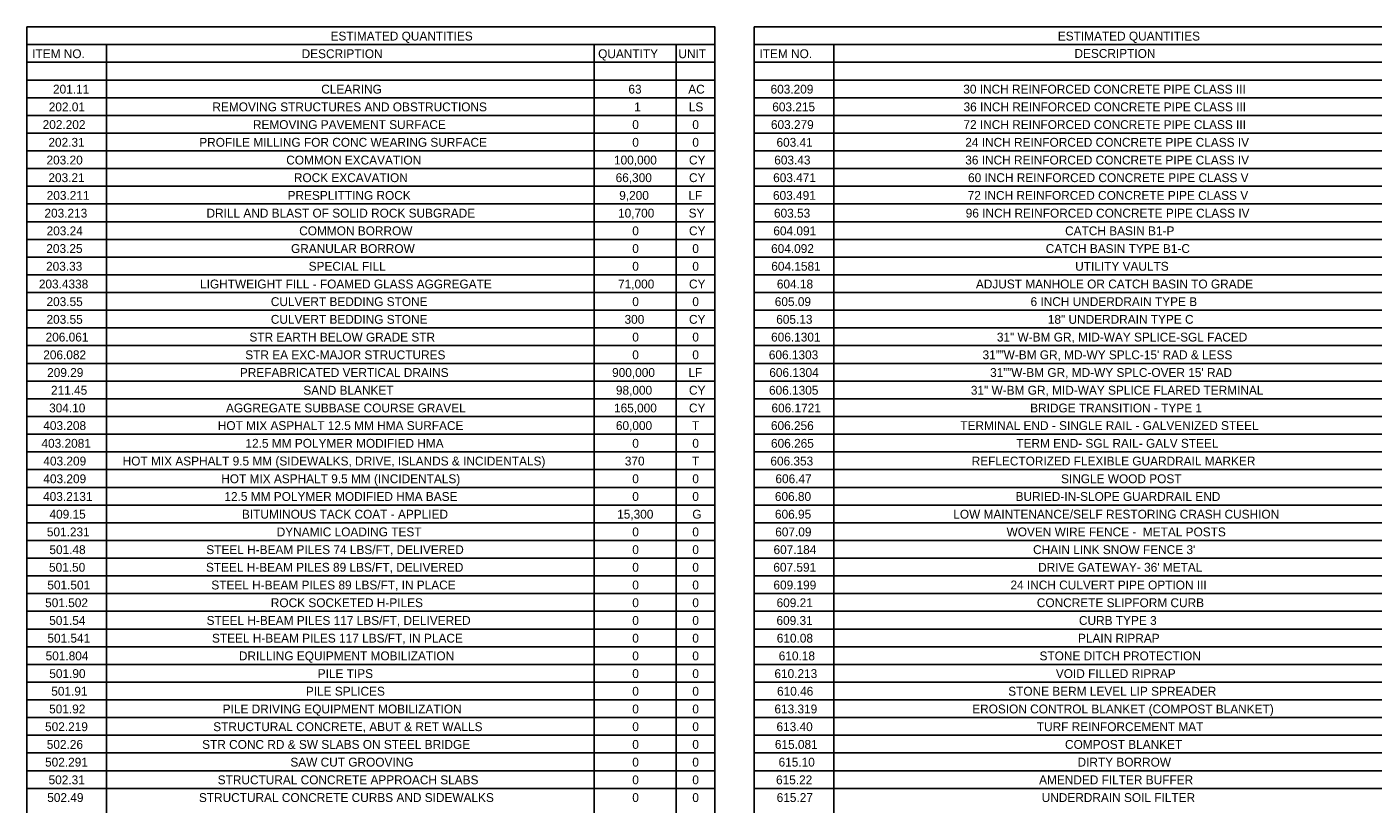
# Model space of a CAD drawing. Extents: x -18.7 to 5.6, y -2.7 to 4.
# Drawn here: x 3.137 to 4.632, y 0.887 to 1.751 of the extents above; entities that cross this region are included whole.
import ezdxf

# ---------------------------------------------------------------- set-up
doc = ezdxf.new("R2010")
doc.units = 0
doc.layers.add('ANNOTATION', color=7, linetype='Continuous')
doc.layers.add('BORDER', color=7, linetype='Continuous')

msp = doc.modelspace()

# ---------------------------------------------------------------- linework, layer by layer
at = {"layer": 'BORDER'}
for p, q in [((3.1369, 1.7315), (3.9012, 1.7315)), ((3.2255, 1.7315), (3.2255, 0.0189)), ((3.7669, 1.7315), (3.7669, 0.0189)), ((3.8583, 1.7315), (3.8583, 0.0189)), ((3.9448, 1.7315), (4.8091, 1.7315)), ((4.0334, 1.7315), (4.0334, 0.0189)), ((3.1369, 1.7119), (3.9012, 1.7119)), ((3.9448, 1.7119), (4.8091, 1.7119)), ((3.1369, 1.6922), (3.9012, 1.6922)), ((3.9448, 1.6922), (4.8091, 1.6922)), ((3.1369, 1.6725), (3.9012, 1.6725)), ((3.9448, 1.6725), (4.8091, 1.6725)), ((3.1369, 1.6528), (3.9012, 1.6528)), ((3.9448, 1.6528), (4.8091, 1.6528)), ((3.1369, 1.6331), (3.9012, 1.6331)), ((3.9448, 1.6331), (4.8091, 1.6331)), ((3.1369, 1.6134), (3.9012, 1.6134)), ((3.9448, 1.6134), (4.8091, 1.6134)), ((3.1369, 1.5937), (3.9012, 1.5937)), ((3.9448, 1.5937), (4.8091, 1.5937)), ((3.1369, 1.5741), (3.9012, 1.5741)), ((3.9448, 1.5741), (4.8091, 1.5741)), ((3.1369, 1.5544), (3.9012, 1.5544)), ((3.9448, 1.5544), (4.8091, 1.5544)), ((3.1369, 1.5347), (3.9012, 1.5347)), ((3.9448, 1.5347), (4.8091, 1.5347)), ((3.1369, 1.515), (3.9012, 1.515)), ((3.9448, 1.515), (4.8091, 1.515)), ((3.1369, 1.4953), (3.9012, 1.4953)), ((3.9448, 1.4953), (4.8091, 1.4953)), ((3.1369, 1.4756), (3.9012, 1.4756)), ((3.9448, 1.4756), (4.8091, 1.4756)), ((3.1369, 1.4559), (3.9012, 1.4559)), ((3.9448, 1.4559), (4.8091, 1.4559)), ((3.1369, 1.4363), (3.9012, 1.4363)), ((3.9448, 1.4363), (4.8091, 1.4363)), ((3.1369, 1.4166), (3.9012, 1.4166)), ((3.9448, 1.4166), (4.8091, 1.4166)), ((3.1369, 1.3969), (3.9012, 1.3969)), ((3.9448, 1.3969), (4.8091, 1.3969)), ((3.1369, 1.3772), (3.9012, 1.3772)), ((3.9448, 1.3772), (4.8091, 1.3772)), ((3.1369, 1.3575), (3.9012, 1.3575)), ((3.9448, 1.3575), (4.8091, 1.3575)), ((3.1369, 1.3378), (3.9012, 1.3378)), ((3.9448, 1.3378), (4.8091, 1.3378)), ((3.1369, 1.3181), (3.9012, 1.3181)), ((3.9448, 1.3181), (4.8091, 1.3181)), ((3.1369, 1.2985), (3.9012, 1.2985)), ((3.9448, 1.2985), (4.8091, 1.2985)), ((3.1369, 1.2788), (3.9012, 1.2788)), ((3.9448, 1.2788), (4.8091, 1.2788)), ((3.1369, 1.2591), (3.9012, 1.2591)), ((3.9448, 1.2591), (4.8091, 1.2591)), ((3.1369, 1.2394), (3.9012, 1.2394)), ((3.9448, 1.2394), (4.8091, 1.2394)), ((3.1369, 1.2197), (3.9012, 1.2197)), ((3.9448, 1.2197), (4.8091, 1.2197)), ((3.1369, 1.2), (3.9012, 1.2)), ((3.9448, 1.2), (4.8091, 1.2)), ((3.1369, 1.1803), (3.9012, 1.1803)), ((3.9448, 1.1803), (4.8091, 1.1803)), ((3.1369, 1.1607), (3.9012, 1.1607)), ((3.9448, 1.1607), (4.8091, 1.1607)), ((3.1369, 1.141), (3.9012, 1.141)), ((3.9448, 1.141), (4.8091, 1.141)), ((3.1369, 1.1213), (3.9012, 1.1213)), ((3.9448, 1.1213), (4.8091, 1.1213)), ((3.1369, 1.1016), (3.9012, 1.1016)), ((3.9448, 1.1016), (4.8091, 1.1016)), ((3.1369, 1.0819), (3.9012, 1.0819)), ((3.9448, 1.0819), (4.8091, 1.0819)), ((3.1369, 1.0622), (3.9012, 1.0622)), ((3.9448, 1.0622), (4.8091, 1.0622)), ((3.1369, 1.0425), (3.9012, 1.0425)), ((3.9448, 1.0425), (4.8091, 1.0425)), ((3.1369, 1.0229), (3.9012, 1.0229)), ((3.9448, 1.0229), (4.8091, 1.0229)), ((3.1369, 1.0032), (3.9012, 1.0032)), ((3.9448, 1.0032), (4.8091, 1.0032)), ((3.1369, 0.9835), (3.9012, 0.9835)), ((3.9448, 0.9835), (4.8091, 0.9835)), ((3.1369, 0.9638), (3.9012, 0.9638)), ((3.9448, 0.9638), (4.8091, 0.9638)), ((3.1369, 0.9441), (3.9012, 0.9441)), ((3.9448, 0.9441), (4.8091, 0.9441)), ((3.1369, 0.9244), (3.9012, 0.9244)), ((3.9448, 0.9244), (4.8091, 0.9244)), ((3.1369, 0.9047), (3.9012, 0.9047)), ((3.9448, 0.9047), (4.8091, 0.9047))]:
    msp.add_line(p, q, dxfattribs=at)
for points in [[(3.1369, 1.7512), (3.9012, 1.7512), (3.9012, 0.0189), (3.1369, 0.0189)], [(3.9448, 1.7512), (4.8091, 1.7512), (4.8091, 0.0189), (3.9448, 0.0189)]]:
    msp.add_lwpolyline(points, close=True, dxfattribs=at)

# ---------------------------------------------------------------- texts
at = {"layer": 'ANNOTATION'}
for s, height, p in [('201.11', 0.00984, (3.1659, 1.6771)), ('CLEARING', 0.00984, (3.4639, 1.6771)), ('63', 0.00984, (3.8051, 1.6771)), ('AC', 0.00984, (3.8716, 1.6771)), ('603.209', 0.00984, (3.963, 1.6771)), ('30 INCH REINFORCED CONCRETE PIPE CLASS III', 0.009843, (4.1771, 1.6771)), ('202.01', 0.00984, (3.1612, 1.6574)), ('REMOVING STRUCTURES AND OBSTRUCTIONS', 0.009843, (3.343, 1.6574)), ('1', 0.00984, (3.8115, 1.6574)), ('LS', 0.00984, (3.8722, 1.6574)), ('603.215', 0.00984, (3.9649, 1.6574)), ('36 INCH REINFORCED CONCRETE PIPE CLASS III', 0.009843, (4.1774, 1.6574)), ('202.202', 0.00984, (3.1544, 1.6377)), ('REMOVING PAVEMENT SURFACE', 0.009843, (3.388, 1.6377)), ('0', 0.00984, (3.8094, 1.6377)), ('0', 0.00984, (3.8761, 1.6377)), ('603.279', 0.00984, (3.9634, 1.6377)), ('72 INCH REINFORCED CONCRETE PIPE CLASS III', 0.009843, (4.1773, 1.6377)), ('202.31', 0.00984, (3.1608, 1.618)), ('PROFILE MILLING FOR CONC WEARING SURFACE', 0.009843, (3.3284, 1.618)), ('0', 0.00984, (3.8094, 1.618)), ('0', 0.00984, (3.8761, 1.618)), ('603.41', 0.00984, (3.9696, 1.618)), ('24 INCH REINFORCED CONCRETE PIPE CLASS IV', 0.009843, (4.1793, 1.618)), ('203.20', 0.00984, (3.1587, 1.5983)), ('COMMON EXCAVATION', 0.009843, (3.425, 1.5983)), ('100,000', 0.00984, (3.7891, 1.5983)), ('CY', 0.00984, (3.8724, 1.5983)), ('603.43', 0.00984, (3.9671, 1.5983)), ('36 INCH REINFORCED CONCRETE PIPE CLASS IV', 0.009843, (4.1793, 1.5983)), ('203.21', 0.00984, (3.1608, 1.5787)), ('ROCK EXCAVATION', 0.009843, (3.4335, 1.5787)), ('66,300', 0.00984, (3.7909, 1.5787)), ('CY', 0.00984, (3.8724, 1.5787)), ('603.471', 0.00984, (3.9659, 1.5787)), ('60 INCH REINFORCED CONCRETE PIPE CLASS V', 0.009843, (4.1824, 1.5787)), ('203.211', 0.00984, (3.1589, 1.559)), ('PRESPLITTING ROCK', 0.009843, (3.4265, 1.559)), ('9,200', 0.00984, (3.7949, 1.559)), ('LF', 0.00984, (3.8718, 1.559)), ('603.491', 0.00984, (3.9657, 1.559)), ('72 INCH REINFORCED CONCRETE PIPE CLASS V', 0.009843, (4.182, 1.559)), ('203.213', 0.00984, (3.1564, 1.5393)), ('DRILL AND BLAST OF SOLID ROCK SUBGRADE', 0.009843, (3.3364, 1.5393)), ('10,700', 0.00984, (3.7936, 1.5393)), ('SY', 0.00984, (3.872, 1.5393)), ('603.53', 0.00984, (3.9668, 1.5393)), ('96 INCH REINFORCED CONCRETE PIPE CLASS IV', 0.009843, (4.1798, 1.5393)), ('203.24', 0.00984, (3.1588, 1.5196)), ('COMMON BORROW', 0.009843, (3.4394, 1.5196)), ('0', 0.00984, (3.8094, 1.5196)), ('CY', 0.00984, (3.8724, 1.5196)), ('604.091', 0.00984, (3.9661, 1.5196)), ('CATCH BASIN B1-P', 0.009843, (4.2902, 1.5196)), ('203.25', 0.00984, (3.1585, 1.4999)), ('GRANULAR BORROW', 0.009843, (3.4303, 1.4999)), ('0', 0.00984, (3.8094, 1.4999)), ('0', 0.00984, (3.8761, 1.4999)), ('604.092', 0.00984, (3.9636, 1.4999)), ('CATCH BASIN TYPE B1-C', 0.009843, (4.2687, 1.4999)), ('203.33', 0.00984, (3.1582, 1.4802)), ('SPECIAL FILL', 0.009843, (3.4499, 1.4802)), ('0', 0.00984, (3.8094, 1.4802)), ('0', 0.00984, (3.8761, 1.4802)), ('604.1581', 0.00984, (3.9638, 1.4802)), ('UTILITY VAULTS', 0.009843, (4.3014, 1.4802)), ('203.4338', 0.00984, (3.1502, 1.4605)), ('LIGHTWEIGHT FILL - FOAMED GLASS AGGREGATE', 0.009843, (3.3293, 1.4605)), ('71,000', 0.00984, (3.7936, 1.4605)), ('CY', 0.00984, (3.8724, 1.4605)), ('604.18', 0.00984, (3.97, 1.4605)), ('ADJUST MANHOLE OR CATCH BASIN TO GRADE', 0.009843, (4.1911, 1.4605)), ('203.55', 0.00984, (3.1587, 1.4409)), ('CULVERT BEDDING STONE', 0.009843, (3.4079, 1.4409)), ('0', 0.00984, (3.8094, 1.4409)), ('0', 0.00984, (3.8761, 1.4409)), ('605.09', 0.00984, (3.9677, 1.4409)), ('6 INCH UNDERDRAIN TYPE B', 0.009843, (4.2518, 1.4409)), ('203.55', 0.00984, (3.1587, 1.4212)), ('CULVERT BEDDING STONE', 0.009843, (3.4079, 1.4212)), ('300', 0.00984, (3.8008, 1.4212)), ('CY', 0.00984, (3.8724, 1.4212)), ('605.13', 0.00984, (3.9693, 1.4212)), ('18" UNDERDRAIN TYPE C', 0.009843, (4.271, 1.4212)), ('206.061', 0.00984, (3.1577, 1.4015)), ('STR EARTH BELOW GRADE STR', 0.009843, (3.3841, 1.4015)), ('0', 0.00984, (3.8094, 1.4015)), ('0', 0.00984, (3.8761, 1.4015)), ('606.1301', 0.00984, (3.9636, 1.4015)), ('31" W-BM GR, MID-WAY SPLICE-SGL FACED', 0.009843, (4.2144, 1.4015)), ('206.082', 0.00984, (3.1551, 1.3818)), ('STR EA EXC-MAJOR STRUCTURES', 0.009843, (3.3795, 1.3818)), ('0', 0.00984, (3.8094, 1.3818)), ('0', 0.00984, (3.8761, 1.3818)), ('606.1303', 0.00984, (3.9611, 1.3818)), ("31””W-BM GR, MD-WY SPLC-15' RAD & LESS", 0.009843, (4.1985, 1.3818)), ('209.29', 0.00984, (3.1594, 1.3621)), ('PREFABRICATED VERTICAL DRAINS', 0.009843, (3.3735, 1.3621)), ('900,000', 0.00984, (3.787, 1.3621)), ('LF', 0.00984, (3.8718, 1.3621)), ('606.1304', 0.00984, (3.9616, 1.3621)), ("31””W-BM GR, MD-WY SPLC-OVER 15' RAD", 0.009843, (4.2069, 1.3621)), ('211.45', 0.00984, (3.1637, 1.3424)), ('SAND BLANKET', 0.009843, (3.444, 1.3424)), ('98,000', 0.00984, (3.7912, 1.3424)), ('CY', 0.00984, (3.8724, 1.3424)), ('606.1305', 0.00984, (3.9613, 1.3424)), ('31" W-BM GR, MID-WAY SPLICE FLARED TERMINAL', 0.009843, (4.1855, 1.3424)), ('304.10', 0.00984, (3.1616, 1.3227)), ('AGGREGATE SUBBASE COURSE GRAVEL', 0.009843, (3.3581, 1.3227)), ('165,000', 0.00984, (3.7891, 1.3227)), ('CY', 0.00984, (3.8724, 1.3227)), ('606.1721', 0.00984, (3.964, 1.3227)), ('BRIDGE TRANSITION - TYPE 1', 0.009843, (4.2514, 1.3227)), ('403.208', 0.00984, (3.1551, 1.3031)), ('HOT MIX ASPHALT 12.5 MM HMA SURFACE', 0.009843, (3.349, 1.3031)), ('60,000', 0.00984, (3.7912, 1.3031)), ('T', 0.00984, (3.8757, 1.3031)), ('606.256', 0.00984, (3.9634, 1.3031)), ('TERMINAL END - SINGLE RAIL - GALVENIZED STEEL', 0.009843, (4.1738, 1.3031)), ('403.2081', 0.00984, (3.1531, 1.2834)), ('12.5 MM POLYMER MODIFIED HMA', 0.009843, (3.3797, 1.2834)), ('0', 0.00984, (3.8094, 1.2834)), ('0', 0.00984, (3.8761, 1.2834)), ('606.265', 0.00984, (3.9635, 1.2834)), ('TERM END- SGL RAIL- GALV STEEL', 0.009843, (4.236, 1.2834)), ('403.209', 0.00984, (3.1552, 1.2637)), ('HOT MIX ASPHALT 9.5 MM (SIDEWALKS, DRIVE, ISLANDS & INCIDENTALS)', 0.009843, (3.2433, 1.2637)), ('370', 0.00984, (3.8011, 1.2637)), ('T', 0.00984, (3.8757, 1.2637)), ('606.353', 0.00984, (3.9628, 1.2637)), ('REFLECTORIZED FLEXIBLE GUARDRAIL MARKER', 0.009843, (4.1864, 1.2637)), ('403.209', 0.00984, (3.1552, 1.244)), ('HOT MIX ASPHALT 9.5 MM (INCIDENTALS)', 0.009843, (3.3528, 1.244)), ('0', 0.00984, (3.8094, 1.244)), ('0', 0.00984, (3.8761, 1.244)), ('606.47', 0.00984, (3.9684, 1.244)), ('SINGLE WOOD POST', 0.009843, (4.2857, 1.244)), ('403.2131', 0.00984, (3.1549, 1.2243)), ('12.5 MM POLYMER MODIFIED HMA BASE', 0.009843, (3.3563, 1.2243)), ('0', 0.00984, (3.8094, 1.2243)), ('0', 0.00984, (3.8761, 1.2243)), ('606.80', 0.00984, (3.9678, 1.2243)), ('BURIED-IN-SLOPE GUARDRAIL END', 0.009843, (4.2352, 1.2243)), ('409.15', 0.00984, (3.162, 1.2046)), ('BITUMINOUS TACK COAT - APPLIED', 0.009843, (3.3758, 1.2046)), ('15,300', 0.00984, (3.7926, 1.2046)), ('G', 0.00984, (3.8761, 1.2046)), ('606.95', 0.00984, (3.9679, 1.2046)), ('LOW MAINTENANCE/SELF RESTORING CRASH CUSHION', 0.009843, (4.166, 1.2046)), ('501.231', 0.00984, (3.1591, 1.1849)), ('DYNAMIC LOADING TEST', 0.009843, (3.4144, 1.1849)), ('0', 0.00984, (3.8094, 1.1849)), ('0', 0.00984, (3.8761, 1.1849)), ('607.09', 0.00984, (3.9682, 1.1849)), ('WOVEN WIRE FENCE -  METAL POSTS', 0.009843, (4.2252, 1.1849)), ('501.48', 0.00984, (3.1619, 1.1652)), ('STEEL H-BEAM PILES 74 LBS/FT, DELIVERED', 0.009843, (3.3362, 1.1652)), ('0', 0.00984, (3.8094, 1.1652)), ('0', 0.00984, (3.8761, 1.1652)), ('607.184', 0.00984, (3.9663, 1.1652)), ("CHAIN LINK SNOW FENCE 3'", 0.009843, (4.2546, 1.1652)), ('501.50', 0.00984, (3.1615, 1.1456)), ('STEEL H-BEAM PILES 89 LBS/FT, DELIVERED', 0.009843, (3.3358, 1.1456)), ('0', 0.00984, (3.8094, 1.1456)), ('0', 0.00984, (3.8761, 1.1456)), ('607.591', 0.00984, (3.9661, 1.1456)), ("DRIVE GATEWAY- 36' METAL", 0.009843, (4.2602, 1.1456)), ('501.501', 0.00984, (3.1596, 1.1259)), ('STEEL H-BEAM PILES 89 LBS/FT, IN PLACE', 0.009843, (3.3418, 1.1259)), ('0', 0.00984, (3.8094, 1.1259)), ('0', 0.00984, (3.8761, 1.1259)), ('609.199', 0.00984, (3.9662, 1.1259)), ('24 INCH CULVERT PIPE OPTION III', 0.009843, (4.2295, 1.1259)), ('501.502', 0.00984, (3.1572, 1.1062)), ('ROCK SOCKETED H-PILES', 0.009843, (3.4079, 1.1062)), ('0', 0.00984, (3.8094, 1.1062)), ('0', 0.00984, (3.8761, 1.1062)), ('609.21', 0.00984, (3.9697, 1.1062)), ('CONCRETE SLIPFORM CURB', 0.009843, (4.2588, 1.1062)), ('501.54', 0.00984, (3.1617, 1.0865)), ('STEEL H-BEAM PILES 117 LBS/FT, DELIVERED', 0.009843, (3.3365, 1.0865)), ('0', 0.00984, (3.8094, 1.0865)), ('0', 0.00984, (3.8761, 1.0865)), ('609.31', 0.00984, (3.9696, 1.0865)), ('CURB TYPE 3', 0.009843, (4.3056, 1.0865)), ('501.541', 0.00984, (3.1597, 1.0668)), ('STEEL H-BEAM PILES 117 LBS/FT, IN PLACE', 0.009843, (3.3425, 1.0668)), ('0', 0.00984, (3.8094, 1.0668)), ('0', 0.00984, (3.8761, 1.0668)), ('610.08', 0.00984, (3.9699, 1.0668)), ('PLAIN RIPRAP', 0.009843, (4.3045, 1.0668)), ('501.804', 0.00984, (3.1577, 1.0471)), ('DRILLING EQUIPMENT MOBILIZATION', 0.009843, (3.3724, 1.0471)), ('0', 0.00984, (3.8094, 1.0471)), ('0', 0.00984, (3.8761, 1.0471)), ('610.18', 0.00984, (3.9721, 1.0471)), ('STONE DITCH PROTECTION', 0.009843, (4.2618, 1.0471)), ('501.90', 0.00984, (3.1618, 1.0274)), ('PILE TIPS', 0.00984, (3.46, 1.0274)), ('0', 0.00984, (3.8094, 1.0274)), ('0', 0.00984, (3.8761, 1.0274)), ('610.213', 0.00984, (3.9673, 1.0274)), ('VOID FILLED RIPRAP', 0.009843, (4.2799, 1.0274)), ('501.91', 0.00984, (3.164, 1.0078)), ('PILE SPLICES', 0.009843, (3.4468, 1.0078)), ('0', 0.00984, (3.8094, 1.0078)), ('0', 0.00984, (3.8761, 1.0078)), ('610.46', 0.00984, (3.9702, 1.0078)), ('STONE BERM LEVEL LIP SPREADER ', 0.009843, (4.227, 1.0078)), ('501.92', 0.00984, (3.1616, 0.9881)), ('PILE DRIVING EQUIPMENT MOBILIZATION', 0.009843, (3.3544, 0.9881)), ('0', 0.00984, (3.8094, 0.9881)), ('0', 0.00984, (3.8761, 0.9881)), ('613.319', 0.00984, (3.9673, 0.9881)), ('EROSION CONTROL BLANKET (COMPOST BLANKET)', 0.009843, (4.187, 0.9881)), ('502.219', 0.00984, (3.1571, 0.9684)), ('STRUCTURAL CONCRETE, ABUT & RET WALLS', 0.009843, (3.3439, 0.9684)), ('0', 0.00984, (3.8094, 0.9684)), ('0', 0.00984, (3.8761, 0.9684)), ('613.40', 0.00984, (3.9696, 0.9684)), ('TURF REINFORCEMENT MAT', 0.009843, (4.2588, 0.9684)), ('502.26', 0.00984, (3.159, 0.9487)), ('STR CONC RD & SW SLABS ON STEEL BRIDGE', 0.009843, (3.3316, 0.9487)), ('0', 0.00984, (3.8094, 0.9487)), ('0', 0.00984, (3.8761, 0.9487)), ('615.081', 0.00984, (3.9678, 0.9487)), ('COMPOST BLANKET', 0.009843, (4.2901, 0.9487)), ('502.291', 0.00984, (3.1571, 0.929)), ('SAW CUT GROOVING', 0.009843, (3.4296, 0.929)), ('0', 0.00984, (3.8094, 0.929)), ('0', 0.00984, (3.8761, 0.929)), ('615.10', 0.00984, (3.9719, 0.929)), ('DIRTY BORROW', 0.009843, (4.304, 0.929)), ('502.31', 0.00984, (3.161, 0.9093)), ('STRUCTURAL CONCRETE APPROACH SLABS', 0.009843, (3.3489, 0.9093)), ('0', 0.00984, (3.8094, 0.9093)), ('0', 0.00984, (3.8761, 0.9093)), ('615.22', 0.00984, (3.9691, 0.9093)), ('AMENDED FILTER BUFFER', 0.009843, (4.2613, 0.9093)), ('502.49', 0.00984, (3.1595, 0.8896)), ('STRUCTURAL CONCRETE CURBS AND SIDEWALKS', 0.009843, (3.328, 0.8896)), ('0', 0.00984, (3.8094, 0.8896)), ('0', 0.00984, (3.8761, 0.8896)), ('615.27', 0.00984, (3.9698, 0.8896)), ('UNDERDRAIN SOIL FILTER', 0.009843, (4.2642, 0.8896))]:
    msp.add_text(s, height=height, dxfattribs=at).set_placement(p)
at = {"layer": 'BORDER'}
for s, height, p in [('ESTIMATED QUANTITIES', 0.009843, (3.4742, 1.7361)), ('ESTIMATED QUANTITIES', 0.009843, (4.2821, 1.7361)), ('ITEM NO.', 0.00984, (3.1428, 1.7165)), ('DESCRIPTION', 0.009843, (3.4421, 1.7165)), ('QUANTITY', 0.00984, (3.7715, 1.7165)), ('UNIT', 0.00984, (3.8606, 1.7165)), ('ITEM NO.', 0.00984, (3.9507, 1.7165)), ('DESCRIPTION', 0.009843, (4.3006, 1.7168))]:
    msp.add_text(s, height=height, dxfattribs=at).set_placement(p)

doc.saveas('drawing.dxf')
